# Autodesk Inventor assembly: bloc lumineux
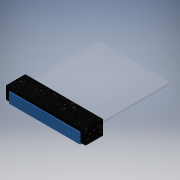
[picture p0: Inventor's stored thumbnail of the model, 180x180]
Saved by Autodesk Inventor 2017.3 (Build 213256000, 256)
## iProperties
Part Number: bloc lumineux
Material: Générique
Document SubType Name: Assembly
Designer: ficho
Author: ficho
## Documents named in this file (8)
- C:\Users\ficho\Desktop\réforme\activité rentrée\bloc lumineux.iam
- C:\Users\ficho\Desktop\réforme\activité rentrée\base fixe.ipt
- C:\Users\ficho\Desktop\réforme\activité rentrée\stick neopixel 8 leds.iam
- C:\Users\ficho\Desktop\réforme\activité rentrée\base tournante.ipt
- C:\Users\ficho\Desktop\réforme\activité rentrée\plaque pmma vierge.ipt
- C:\Users\ficho\Desktop\réforme\activité rentrée\axe de rotation du bloc.ipt
- C:\Users\ficho\OneDrive\Documents\Inventor\Content Center Files\R2017\fr-FR\ISO 7046-1 H(1)\ISO 7046-1 - M1,6 x 3 - 4.8 - H - ISO.ipt
- C:\Users\ficho\OneDrive\Documents\Inventor\Content Center Files\R2017\fr-FR\ISO 7045  Z\ISO 7045 - M2 x 3 - 4.8 - Z - ISO.ipt
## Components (14 placed, 7 different names)
1. base fixe:1 — Placage:1, Placage:2, Placage:3, Placage:5, Affleurement:2
2. stick neopixel 8 leds:1 [sub-assembly] — Placage:1, Placage:4, Affleurement:1
3. stick neopixel 8 leds:2 [sub-assembly] — Placage:2, Placage:3, Placage:4, Placage:5, Affleurement:1
4. base tournante:1 — Affleurement:2, Placage:6, Placage:7, Placage:8, Logement:1, Logement:2
5. plaque pmma vierge:1 — Placage:6, Placage:7, Placage:8
6. axe de rotation du bloc:1 — Logement:2
7. axe de rotation du bloc:2 — Logement:1
8. ISO 7046-1 H M1,6 x 3 - 4.8 - H:1
9. ISO 7045 Z M2 x 3 - 4.8 - Z:1
10. ISO 7045 Z M2 x 3 - 4.8 - Z:2
11. ISO 7045 Z M2 x 3 - 4.8 - Z:3
12. ISO 7045 Z M2 x 3 - 4.8 - Z:4
13. ISO 7045 Z M2 x 3 - 4.8 - Z:5
14. ISO 7045 Z M2 x 3 - 4.8 - Z:6
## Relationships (12: Mate 8, Flush 2, Insert 2)
- Placage:1 [Mate]: base fixe:1 ↔ stick neopixel 8 leds:1
- Placage:2 [Mate]: base fixe:1 ↔ stick neopixel 8 leds:2
- Placage:3 [Mate]: base fixe:1 ↔ stick neopixel 8 leds:2
- Placage:4 [Mate]: stick neopixel 8 leds:1 ↔ stick neopixel 8 leds:2
- Placage:5 [Mate]: base fixe:1 ↔ stick neopixel 8 leds:2
- Affleurement:1 [Flush]: stick neopixel 8 leds:1 ↔ stick neopixel 8 leds:2
- Affleurement:2 [Flush]: base fixe:1 ↔ base tournante:1
- Placage:6 [Mate]: base tournante:1 ↔ plaque pmma vierge:1
- Placage:7 [Mate]: base tournante:1 ↔ plaque pmma vierge:1
- Placage:8 [Mate]: base tournante:1 ↔ plaque pmma vierge:1
- Logement:1 [Insert]: base tournante:1 ↔ axe de rotation du bloc:2
- Logement:2 [Insert]: base tournante:1 ↔ axe de rotation du bloc:1
